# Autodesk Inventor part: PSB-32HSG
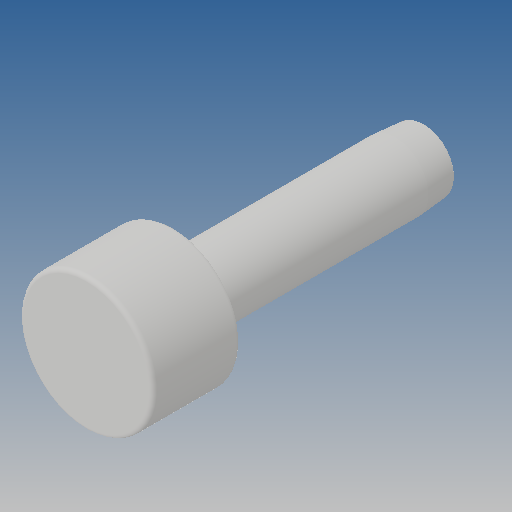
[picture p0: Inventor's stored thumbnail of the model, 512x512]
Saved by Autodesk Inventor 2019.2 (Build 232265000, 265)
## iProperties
Created: 2010-02
Part Number: PSB-32HSG
Material: Ogólny
Document SubType Name: Modeling
Designer: CADENGINEERING4
Density: 1 g/cm^3
Appearance: Domyślna
Author: CADENGINEERING4
Revision Number: 1LAST_VERSION
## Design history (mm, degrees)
feature "Baza1"
node "Bryła1"
